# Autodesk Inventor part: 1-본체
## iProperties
Created: 2014-11
Part Number: 1-본체
Document SubType Name: Modeling
Designer: elite
Density: 2.71 g/cm^3
Material: 알루미늄-6061
Mass: 2885.51 g
Surface Area: 2093.33 cm^2
Volume: 1064.77 cm^3
Author: elite
